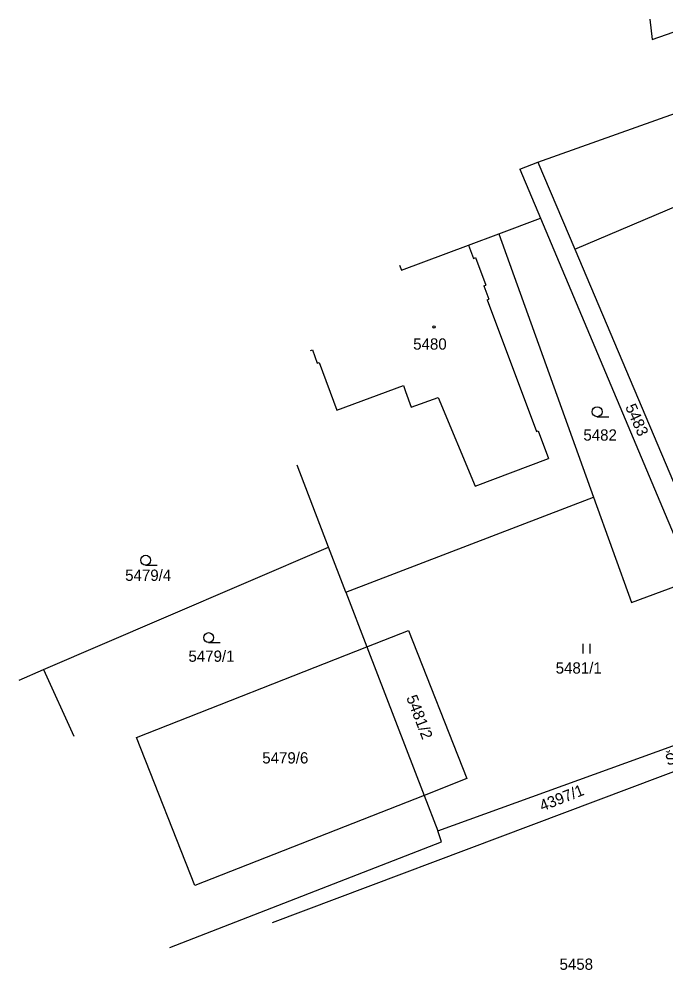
# Model space of a CAD drawing. Extents: x -717507 to -715515, y -957700 to -954941.
# Drawn here: x -716415.9 to -716318.3, y -955443.4 to -955299.8 of the extents above; entities that cross this region are included whole.
import ezdxf

# ---------------------------------------------------------------- set-up
doc = ezdxf.new("R2010")
doc.units = 0
for name, color, linetype in [('Hranice parcel', 7, 'Continuous'), ('Parcelní čísla', 7, 'Continuous'), ('Pop  PČ popisy', 7, 'Continuous'), ('Vnitřní kresba', 7, 'Continuous'), ('Značky budov', 7, 'Continuous'), ('Značky kultur', 7, 'Continuous')]:
    doc.layers.add(name, color=color, linetype=linetype)

msp = doc.modelspace()

# ---------------------------------------------------------------- linework, layer by layer
at = {"layer": 'Hranice parcel'}
for points in [[(-716320.71, -955299.76), (-716320.4, -955302.84)], [(-716320.4, -955302.84), (-716313.88, -955300.58)], [(-716337.65, -955321.38), (-716302, -955308.68)], [(-716340.33, -955322.46), (-716337.65, -955321.38)], [(-716340.33, -955322.46), (-716337.22, -955329.83)], [(-716337.65, -955321.38), (-716332.07, -955334.52)], [(-716332.07, -955334.52), (-716314.74, -955327.19)], [(-716343.52, -955332.19), (-716337.22, -955329.83)], [(-716337.22, -955329.83), (-716314.22, -955384.44)], [(-716343.52, -955332.19), (-716329.25, -955371.95)], [(-716332.07, -955334.52), (-716316.6, -955371.03)], [(-716369.23, -955379.5), (-716373.98, -955367.14)], [(-716366.62, -955386.3), (-716329.25, -955371.95)], [(-716329.25, -955371.95), (-716323.52, -955387.9)], [(-716394.06, -955390.18), (-716369.23, -955379.5)], [(-716366.62, -955386.3), (-716369.23, -955379.5)], [(-716323.52, -955387.9), (-716314.22, -955384.44)], [(-716366.62, -955386.3), (-716363.44, -955394.57)], [(-716412.27, -955398.02), (-716394.06, -955390.18)], [(-716363.44, -955394.57), (-716357.18, -955392.1)], [(-716357.18, -955392.1), (-716348.37, -955414.46)], [(-716398.19, -955408.28), (-716363.44, -955394.57)], [(-716363.44, -955394.57), (-716354.81, -955417)], [(-716415.94, -955399.6), (-716412.27, -955398.02)], [(-716412.27, -955398.02), (-716407.69, -955408.08)], [(-716377.69, -955436.18), (-716289.42, -955402.98)], [(-716352.74, -955422.37), (-716305.46, -955405.23)], [(-716389.4, -955430.64), (-716398.19, -955408.28)], [(-716348.37, -955414.46), (-716354.81, -955417)], [(-716354.81, -955417), (-716389.4, -955430.64)], [(-716354.81, -955417), (-716352.74, -955422.37)], [(-716352.16, -955424.01), (-716352.74, -955422.37)], [(-716393.19, -955439.96), (-716352.16, -955424.01)]]:
    msp.add_lwpolyline(points, dxfattribs=at)
at = {"layer": 'Vnitřní kresba'}
for points in [[(-716348.1, -955333.9), (-716343.52, -955332.19)], [(-716358.21, -955337.67), (-716348.1, -955333.9)], [(-716348.1, -955333.9), (-716347.35, -955335.91)], [(-716358.49, -955336.91), (-716358.21, -955337.67)], [(-716347.35, -955335.91), (-716347.06, -955335.8)], [(-716347.06, -955335.8), (-716345.5, -955339.97)], [(-716345.77, -955340.07), (-716345.5, -955339.97)], [(-716345.77, -955340.07), (-716345.02, -955342.07)], [(-716345.26, -955342.16), (-716345.02, -955342.07)], [(-716345.26, -955342.16), (-716337.82, -955362.07)], [(-716371.95, -955349.83), (-716371.67, -955349.73)], [(-716371.67, -955349.73), (-716370.92, -955351.74)], [(-716370.92, -955351.74), (-716370.66, -955351.64)], [(-716370.66, -955351.64), (-716367.97, -955358.83)], [(-716367.97, -955358.83), (-716357.9, -955355.11)], [(-716357.9, -955355.11), (-716357.59, -955356.01)], [(-716357.59, -955356.01), (-716356.75, -955358.38)], [(-716356.75, -955358.38), (-716352.69, -955356.94)], [(-716352.69, -955356.94), (-716347.1, -955370.3)], [(-716337.82, -955362.07), (-716337.56, -955361.97)], [(-716337.56, -955361.97), (-716336, -955366.13)], [(-716347.1, -955370.3), (-716336, -955366.13)]]:
    msp.add_lwpolyline(points, dxfattribs=at)
at = {"layer": 'Značky budov'}
msp.add_circle((-716353.3, -955346.27), 0.175, dxfattribs=at)
at = {"layer": 'Značky kultur'}
for points in [[(-716328.68, -955359.82), (-716326.93, -955359.82)], [(-716396.83, -955382.24), (-716395.08, -955382.24)], [(-716387.32, -955393.93), (-716385.57, -955393.93)], [(-716330.78, -955395.6), (-716330.78, -955394.1)], [(-716329.74, -955395.6), (-716329.74, -955394.1)]]:
    msp.add_lwpolyline(points, dxfattribs=at)
for centre in [(-716328.68, -955359.07), (-716396.83, -955381.49), (-716387.32, -955393.18)]:
    msp.add_circle(centre, 0.75, dxfattribs=at)

# ---------------------------------------------------------------- texts
at = {"layer": 'Parcelní čísla'}
for s, p in [('5480', (-716356.45, -955349.69)), ('5482', (-716330.76, -955363.43)), ('5479/4', (-716399.92, -955384.61)), ('5479/1', (-716390.37, -955396.83)), ('5481/1', (-716334.94, -955398.61)), ('5479/6', (-716379.23, -955412.19)), ('5458', (-716334.36, -955443.35))]:
    msp.add_text(s, height=1.7, dxfattribs=at).set_placement(p)
for s, rotation, p in [('5483', 294.2023, (-716324.48, -955358.33)), ('5481/2', 291.0023, (-716357.52, -955402.23)), ('4397/1', 21.6002, (-716336.97, -955419.44))]:
    msp.add_text(s, height=1.7, rotation=rotation, dxfattribs=at).set_placement(p)
at = {"layer": 'Pop  PČ popisy'}
msp.add_text('Školní', height=1.7, rotation=18.3001, dxfattribs=at).set_placement((-716318.07, -955412.54))

doc.saveas('drawing.dxf')
